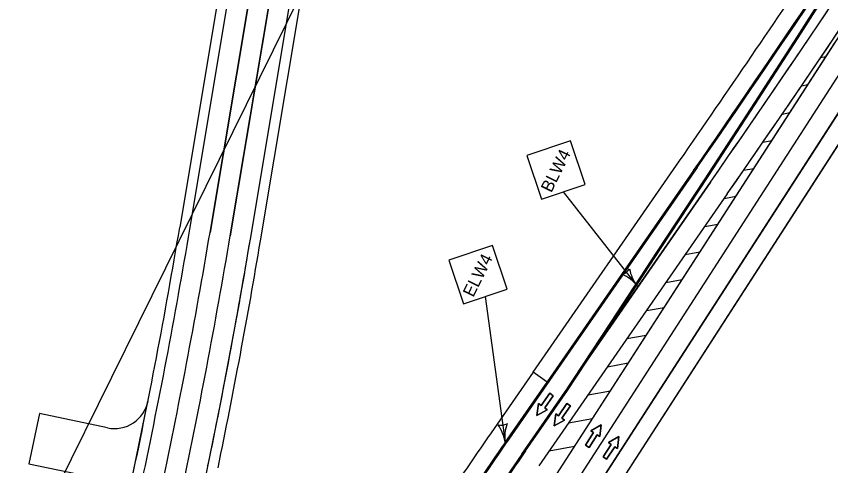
# Model space of a CAD drawing. Extents: x 14090526 to 14125274, y 8637242 to 8677144.
# Drawn here: x 14118917.5 to 14119395, y 8669002.7 to 8669266 of the extents above; entities that cross this region are included whole.
import ezdxf

# ---------------------------------------------------------------- set-up
doc = ezdxf.new("R2010")
doc.units = 0
for name, color, linetype in [('dsn_stg_shd_prev', 7, 'Continuous'), ('dsnNonPlotable', 7, 'Continuous'), ('dsnPaintExistingBrokenLaneLineWhite', 7, 'Continuous'), ('dsnPaintExistingChannelizingLaneYellow', 7, 'Continuous'), ('dsnPaintExistingEdgeLineRightWhite', 7, 'Continuous'), ('dsnPaintPlaceBrokenLineWhite', 7, 'Continuous'), ('dsnPaintPlaceEdgeLineRightWhite', 7, 'Continuous'), ('dsnShadingPaved', 7, 'Continuous'), ('dsnStdLabel', 7, 'Continuous'), ('dsnStgShadingPropPav', 7, 'Continuous'), ('dsnTapeRemoveChannelizingLaneWhite', 7, 'Continuous'), ('Level 2', 7, 'Continuous'), ('Level 5', 7, 'Continuous')]:
    doc.layers.add(name, color=color, linetype=linetype)

msp = doc.modelspace()

# ---------------------------------------------------------------- linework, layer by layer
at = {"layer": 'dsn_stg_shd_prev'}
for p, q in [((14119060.64, 8669134.39), (14119230.09, 8670146.06)), ((14119151.79, 8669969.11), (14119013.3, 8669142.32)), ((14118931.03, 8669033.2), (14118924.89, 8669003.83)), ((14118970.99, 8669024.85), (14118931.03, 8669033.2)), ((14118924.89, 8669003.83), (14118965.52, 8668995.35))]:
    msp.add_line(p, q, dxfattribs=at)
for points in [[(14119498.98, 8669345.14), (14119201.18, 8668883.8), (14119172.86, 8668902.61), (14119172.76, 8668902.45), (14119141.1, 8668923.47)], [(14119204.06, 8669016.22), (14119228.66, 8669051.69), (14119220.45, 8669057.39), (14119306.38, 8669181.26)], [(14118981.22, 8668972.92), (14118984.25, 8668989.85), (14118994.69, 8669040.54)]]:
    msp.add_lwpolyline(points, dxfattribs=at)
for centre, radius, start, end in [((14111929.66, 8674298.73), 8978, 325.249705, 326.199346), ((14115585.06, 8669716.53), 3476, 347.93292, 350.49147), ((14115585.06, 8669716.53), 3524, 348.29238, 350.49147), ((14118975.08, 8669044.43), 20, 258.2058, 348.786), ((14123732.96, 8665874.38), 5512, 145.2497, 146.41498)]:
    msp.add_arc(centre, radius, start, end, dxfattribs=at)
at = {"layer": 'dsnNonPlotable'}
msp.add_lwpolyline([(14119315.27, 8668607.09), (14120010, 8670012.23), (14119557.31, 8670236.05), (14118862.58, 8668830.91)], close=True, dxfattribs=at)
at = {"layer": 'dsnPaintExistingBrokenLaneLineWhite'}
for p, q in [((14119031.05, 8669139.34), (14119200.51, 8670151.01)), ((14119212.34, 8670149.03), (14119042.89, 8669137.36)), ((14119527.44, 8669429.79), (14119185.09, 8668899.43))]:
    msp.add_line(p, q, dxfattribs=at)
for radius in [3494, 3506]:
    msp.add_arc((14115585.06, 8669716.53), radius, 347.93292, 350.49147, dxfattribs=at)
at = {"layer": 'dsnPaintExistingChannelizingLaneYellow'}
for p, q in [((14119175.01, 8668905.94), (14119397.41, 8669250.48)), ((14119389.08, 8669241.74), (14119392.15, 8669242.33)), ((14119377.83, 8669225.2), (14119381.55, 8669225.9)), ((14119366.55, 8669208.68), (14119370.96, 8669209.51)), ((14119355.24, 8669192.19), (14119360.4, 8669193.14)), ((14119343.89, 8669175.72), (14119349.86, 8669176.81)), ((14119334.31, 8669161.88), (14119223.77, 8669002.54)), ((14119332.51, 8669159.28), (14119339.34, 8669160.51)), ((14119321.11, 8669142.84), (14119328.83, 8669144.24)), ((14119309.71, 8669126.41), (14119318.33, 8669127.97)), ((14119298.31, 8669109.98), (14119307.83, 8669111.7)), ((14119286.91, 8669093.55), (14119297.32, 8669095.43)), ((14119275.51, 8669077.11), (14119286.82, 8669079.16)), ((14119264.11, 8669060.68), (14119276.32, 8669062.89)), ((14119252.71, 8669044.25), (14119265.82, 8669046.62)), ((14119241.31, 8669027.81), (14119255.31, 8669030.35)), ((14119229.91, 8669011.38), (14119244.81, 8669014.08))]:
    msp.add_line(p, q, dxfattribs=at)
msp.add_arc((14111644.26, 8674494.18), 9357.9, 325.262476, 326.828528, dxfattribs=at)
at = {"layer": 'dsnPaintExistingEdgeLineRightWhite'}
msp.add_line((14119195.17, 8668892.92), (14119537.53, 8669423.29), dxfattribs=at)
for centre, radius, start, end in [((14111644.26, 8674494.18), 9333.9, 325.262476, 326.828528), ((14115585.06, 8669716.53), 3482, 347.93292, 350.49147), ((14115585.06, 8669716.53), 3518, 348.29238, 350.49147)]:
    msp.add_arc(centre, radius, start, end, dxfattribs=at)
at = {"layer": 'dsnPaintPlaceBrokenLineWhite'}
msp.add_line((14119324.45, 8669168.72), (14119213.91, 8669009.38), dxfattribs=at)
for centre, radius, start, end in [((14111644.26, 8674494.18), 9345.9, 325.262476, 326.828528), ((14123732.96, 8665874.38), 5500, 145.2497, 146.42378)]:
    msp.add_arc(centre, radius, start, end, dxfattribs=at)
at = {"layer": 'dsnPaintPlaceEdgeLineRightWhite'}
msp.add_line((14119314.59, 8669175.56), (14119204.06, 8669016.22), dxfattribs=at)
msp.add_arc((14123732.96, 8665874.38), 5512, 145.2497, 146.41498, dxfattribs=at)
at = {"layer": 'dsnShadingPaved'}
for p, q in [((14119019.22, 8669141.32), (14119188.67, 8670153)), ((14119200.51, 8670151.01), (14119031.05, 8669139.34)), ((14119200.51, 8670151.01), (14119031.05, 8669139.34)), ((14119212.34, 8670149.03), (14119042.89, 8669137.36)), ((14119042.89, 8669137.36), (14119212.34, 8670149.03)), ((14119054.72, 8669135.38), (14119224.18, 8670147.05)), ((14119175.01, 8668905.94), (14119517.35, 8669436.29)), ((14119316.73, 8669177.46), (14119206.19, 8669018.12)), ((14119213.91, 8669009.38), (14119324.45, 8669168.72)), ((14119324.45, 8669168.72), (14119238.52, 8669044.85)), ((14119334.31, 8669161.88), (14119223.77, 8669002.54)), ((14119216.05, 8669011.28), (14119240.66, 8669046.75))]:
    msp.add_line(p, q, dxfattribs=at)
for points in [[(14119240.66, 8669046.75), (14119268.13, 8669088.55), (14119295.6, 8669130.34), (14119323.07, 8669172.14), (14119350.44, 8669214.01), (14119377.59, 8669256.06), (14119404.49, 8669298.25), (14119431.16, 8669340.59), (14119457.59, 8669383.07), (14119483.78, 8669425.69), (14119499.48, 8669451.39)], [(14119238.52, 8669044.85), (14119265.99, 8669086.65), (14119293.47, 8669128.44), (14119320.94, 8669170.24), (14119348.3, 8669212.11), (14119375.45, 8669254.16), (14119402.36, 8669296.35), (14119429.03, 8669338.69), (14119455.46, 8669381.17), (14119481.65, 8669423.79), (14119497.35, 8669449.49)], [(14119537.53, 8669423.29), (14119537.53, 8669423.29), (14119195.17, 8668892.92)]]:
    msp.add_lwpolyline(points, dxfattribs=at)
for centre, radius, start, end in [((14111929.66, 8674298.73), 9000, 325.249705, 327.157368), ((14111929.66, 8674298.73), 9000, 325.249705, 327.157368), ((14111929.66, 8674298.73), 9012, 325.249705, 327.157368), ((14111646.4, 8674496.08), 9333.9, 325.262476, 326.828528), ((14115585.06, 8669716.53), 3482, 347.93292, 350.49147), ((14115585.06, 8669716.53), 3494, 347.93292, 350.49147), ((14115585.06, 8669716.53), 3494, 347.93292, 350.49147), ((14115585.06, 8669716.53), 3506, 347.93292, 350.49147), ((14115585.06, 8669716.53), 3506, 347.93292, 350.49147), ((14115585.06, 8669716.53), 3518, 347.93292, 350.49147), ((14123735.09, 8665876.28), 5512, 145.2497, 146.41498), ((14123732.96, 8665874.38), 5500, 145.2497, 157.1633), ((14123735.09, 8665876.28), 5500, 145.2497, 146.42378)]:
    msp.add_arc(centre, radius, start, end, dxfattribs=at)
at = {"layer": 'dsnStdLabel'}
for p, q in [((14119238.21, 8669163.06), (14119281.57, 8669107.92)), ((14119192.46, 8669101.77), (14119204.06, 8669016.22))]:
    msp.add_line(p, q, dxfattribs=at)
for points in [[(14119225.42, 8669158.73), (14119250.99, 8669167.39), (14119242.34, 8669192.96), (14119216.77, 8669184.31)], [(14119179.68, 8669097.44), (14119205.25, 8669106.1), (14119196.6, 8669131.67), (14119171.02, 8669123.02)]]:
    msp.add_lwpolyline(points, close=True, dxfattribs=at)
for centre, radius, start, end in [((14119269.68, 8669123.04), 8.86, 290.448, 325.9165), ((14119299.61, 8669122.11), 22.95, 190.111, 218.1823), ((14119263.53, 8669093.73), 22.95, 38.1822, 66.2534), ((14119201.47, 8669035.29), 8.86, 259.9818, 295.4503), ((14119181.31, 8669013.14), 22.95, 7.716, 35.7872), ((14119226.8, 8669019.31), 22.95, 159.6448, 187.7161)]:
    msp.add_arc(centre, radius, start, end, dxfattribs=at)
at = {"layer": 'dsnStgShadingPropPav'}
for p, q in [((14119060.64, 8669134.39), (14119230.09, 8670146.06)), ((14119151.79, 8669969.11), (14119013.3, 8669142.32)), ((14119220.45, 8669057.39), (14119195.84, 8669021.92)), ((14119228.66, 8669051.69), (14119220.45, 8669057.39)), ((14119204.06, 8669016.22), (14119228.66, 8669051.69))]:
    msp.add_line(p, q, dxfattribs=at)
for points in [[(14119420.33, 8669223.29), (14119201.18, 8668883.8), (14119172.86, 8668902.61), (14119172.76, 8668902.45), (14119141.1, 8668923.47)], [(14119204.06, 8669016.22), (14119228.66, 8669051.69), (14119220.45, 8669057.39), (14119306.38, 8669181.26)]]:
    msp.add_lwpolyline(points, dxfattribs=at)
for centre, radius, start, end in [((14111929.66, 8674298.73), 8978, 325.249705, 326.199346), ((14115585.06, 8669716.53), 3476, 347.93292, 350.49147), ((14115585.06, 8669716.53), 3524, 348.29238, 350.49147), ((14123732.96, 8665874.38), 5522, 145.2497, 146.42709), ((14123732.96, 8665874.38), 5512, 145.2497, 146.42562), ((14123732.96, 8665874.38), 5512, 145.2497, 146.41498)]:
    msp.add_arc(centre, radius, start, end, dxfattribs=at)
at = {"layer": 'dsnTapeRemoveChannelizingLaneWhite'}
msp.add_line((14119213.91, 8669009.38), (14119238.52, 8669044.85), dxfattribs=at)
msp.add_lwpolyline([(14119238.52, 8669044.85), (14119265.99, 8669086.65), (14119293.47, 8669128.44), (14119320.94, 8669170.24), (14119348.3, 8669212.11), (14119375.45, 8669254.16), (14119402.36, 8669296.35), (14119429.03, 8669338.69), (14119455.46, 8669381.17), (14119481.65, 8669423.79), (14119497.35, 8669449.49)], dxfattribs=at)
msp.add_arc((14123732.96, 8665874.38), 5500, 145.2497, 146.42378, dxfattribs=at)
at = {"layer": 'Level 2'}
for points in [[(14119232.27, 8669043.69), (14119230.21, 8669045.12), (14119225.22, 8669037.94), (14119223.68, 8669039.01), (14119222.67, 8669032.09), (14119228.81, 8669035.44), (14119227.27, 8669036.51)], [(14119242.36, 8669037.65), (14119240.31, 8669039.08), (14119235.31, 8669031.9), (14119233.77, 8669032.97), (14119232.77, 8669026.05), (14119238.9, 8669029.4), (14119237.36, 8669030.47)], [(14119251.18, 8669014.76), (14119253.28, 8669013.4), (14119258.04, 8669020.74), (14119259.61, 8669019.72), (14119260.39, 8669026.67), (14119254.37, 8669023.12), (14119255.94, 8669022.1)], [(14119261.49, 8669007.81), (14119263.59, 8669006.45), (14119268.35, 8669013.79), (14119269.92, 8669012.78), (14119270.7, 8669019.72), (14119264.68, 8669016.17), (14119266.25, 8669015.15)]]:
    msp.add_lwpolyline(points, close=True, dxfattribs=at)
at = {"layer": 'Level 5'}
for points in [[(14119227.27, 8669036.51), (14119228.81, 8669035.44), (14119222.67, 8669032.09), (14119223.68, 8669039.01), (14119225.22, 8669037.94), (14119230.21, 8669045.12), (14119232.27, 8669043.69), (14119227.27, 8669036.51)], [(14119237.36, 8669030.47), (14119238.9, 8669029.4), (14119232.77, 8669026.05), (14119233.77, 8669032.97), (14119235.31, 8669031.9), (14119240.31, 8669039.08), (14119242.36, 8669037.65), (14119237.36, 8669030.47)], [(14119255.94, 8669022.1), (14119254.37, 8669023.12), (14119260.39, 8669026.67), (14119259.61, 8669019.72), (14119258.04, 8669020.74), (14119253.28, 8669013.4), (14119251.18, 8669014.76), (14119255.94, 8669022.1)], [(14119266.25, 8669015.15), (14119264.68, 8669016.17), (14119270.7, 8669019.72), (14119269.92, 8669012.78), (14119268.35, 8669013.79), (14119263.59, 8669006.45), (14119261.49, 8669007.81), (14119266.25, 8669015.15)]]:
    msp.add_lwpolyline(points, dxfattribs=at)

# ---------------------------------------------------------------- texts
at = {"layer": 'dsnStdLabel'}
for s, p in [('BLW4', (14119231.15, 8669162.2)), ('ELW4', (14119185.4, 8669100.91))]:
    msp.add_text(s, height=7.2, rotation=63.6912, dxfattribs=at).set_placement(p)

doc.saveas('drawing.dxf')
